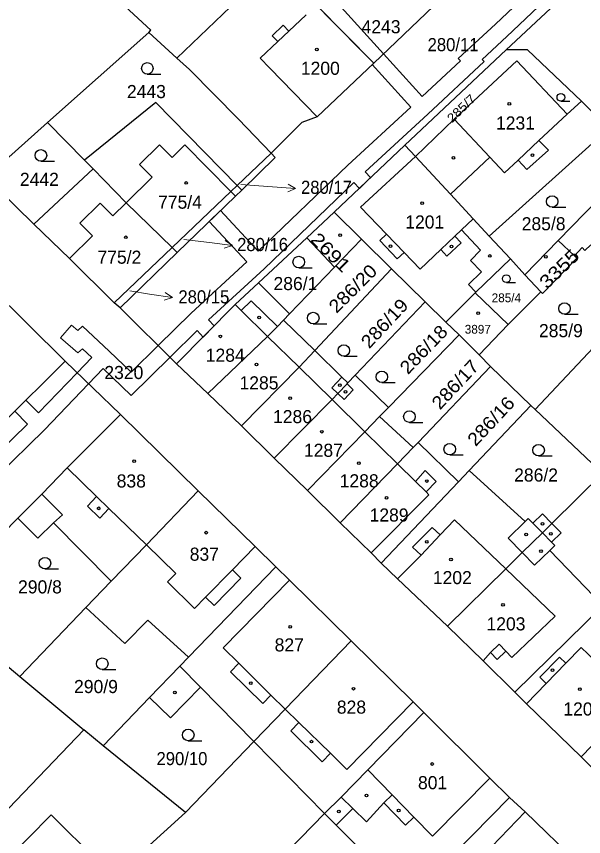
# Model space of a CAD drawing. Extents: x -679733 to -673243, y -1075091 to -1066557.
# Drawn here: x -676204.7 to -676131.1, y -1072172.5 to -1072066.1 of the extents above; entities that cross this region are included whole.
import ezdxf
from ezdxf.enums import TextEntityAlignment as Align

# ---------------------------------------------------------------- set-up
doc = ezdxf.new("R2010")
doc.units = 0
doc.header["$LTSCALE"] = 0.68
for name, color, linetype, lineweight in [('1', 7, 'Continuous', 25), ('13', 7, 'Continuous', 13), ('3', 7, 'Continuous', 25), ('4', 7, 'Continuous', 13), ('5', 7, 'Continuous', 25), ('7', 7, 'Continuous', 13)]:
    doc.layers.add(name, color=color, linetype=linetype, lineweight=lineweight)
doc.layers.add('2', color=7, linetype='Continuous')

msp = doc.modelspace()

# ---------------------------------------------------------------- linework, layer by layer
at = {"layer": '1'}
for p, q in [((-676176.01, -1072088.06), (-676171.6, -1072083.85)), ((-676195.82, -1072084.77), (-676194.71, -1072085.9)), ((-676194.71, -1072085.9), (-676202.38, -1072093.07)), ((-676202.38, -1072093.07), (-676208.61, -1072087)), ((-676175.42, -1072088.66), (-676176.01, -1072088.06)), ((-676134.34, -1072095.2), (-676138.69, -1072099.64)), ((-676134.34, -1072095.2), (-676132.25, -1072097.2)), ((-676183.78, -1072096.77), (-676184.45, -1072096.12)), ((-676138.69, -1072099.64), (-676140.56, -1072097.58)), ((-676169.21, -1072104.69), (-676163.38, -1072098.67)), ((-676155.97, -1072098.88), (-676165.92, -1072109.45)), ((-676191.21, -1072103.95), (-676191.96, -1072103.29)), ((-676147.22, -1072107.44), (-676148.94, -1072105.8)), ((-676160.68, -1072112.67), (-676161.64, -1072113.68)), ((-676137.89, -1072116.59), (-676145.92, -1072125.03)), ((-676191.15, -1072117.78), (-676181.06, -1072127.66)), ((-676147.31, -1072126.49), (-676152.54, -1072121.4)), ((-676171, -1072137.54), (-676182.33, -1072149.26)), ((-676192.35, -1072139.4), (-676195.64, -1072142.82)), ((-676139.96, -1072153.8), (-676128.56, -1072142.56)), ((-676204.23, -1072151.76), (-676195.92, -1072158.68)), ((-676193.42, -1072160.74), (-676187.38, -1072154.49))]:
    msp.add_line(p, q, dxfattribs=at)
for points in [[(-676187.49, -1072068.2), (-676187.22, -1072067.91), (-676195.57, -1072060.17), (-676182.33, -1072048.06), (-676174.16, -1072056.23)], [(-676142.14, -1072056.79), (-676146.87, -1072061.29), (-676150.53, -1072064.78), (-676158.28, -1072072.17)], [(-676172.04, -1072058.35), (-676173.81, -1072060.11), (-676172.9, -1072061.03), (-676183.84, -1072071.54)], [(-676158.28, -1072072.17), (-676165.74, -1072064.68), (-676172.04, -1072058.35)], [(-676154.24, -1072082.84), (-676141.11, -1072070.44), (-676132.12, -1072062.03)], [(-676183.84, -1072071.54), (-676187.49, -1072068.2), (-676200.62, -1072079.87)], [(-676131.34, -1072077.11), (-676138.34, -1072070.44), (-676141.11, -1072070.44)], [(-676171.6, -1072083.85), (-676175.82, -1072079.47), (-676182.21, -1072073.03), (-676183.84, -1072071.54)], [(-676158.28, -1072072.17), (-676165.63, -1072079.13), (-676167.61, -1072079.88), (-676171.6, -1072083.85)], [(-676131.34, -1072077.11), (-676133.21, -1072078.82), (-676139.74, -1072071.87), (-676147.84, -1072079.45), (-676152.89, -1072084.29)], [(-676176.01, -1072088.06), (-676186.55, -1072077.28), (-676195.82, -1072084.77)], [(-676143.32, -1072094.61), (-676127.77, -1072080.68), (-676131.34, -1072077.11)], [(-676195.82, -1072084.77), (-676200.62, -1072079.87), (-676208.61, -1072087)], [(-676143.32, -1072094.61), (-676145.38, -1072092.39), (-676148.34, -1072089.19), (-676152.89, -1072084.29), (-676154.24, -1072082.84), (-676163.44, -1072091.53), (-676159.88, -1072095.04), (-676155.97, -1072098.88), (-676151.61, -1072103.17), (-676148.94, -1072105.8), (-676145.14, -1072101.98)], [(-676171.6, -1072083.85), (-676171.07, -1072084.42), (-676175.42, -1072088.66)], [(-676114.59, -1072093.59), (-676123.94, -1072084.5), (-676134.34, -1072095.2)], [(-676184.45, -1072096.12), (-676190.41, -1072090.29), (-676194.71, -1072085.9)], [(-676184.45, -1072096.12), (-676176.82, -1072088.84), (-676176.01, -1072088.06)], [(-676175.42, -1072088.66), (-676176.24, -1072089.43), (-676183.78, -1072096.77), (-676191.21, -1072103.95), (-676183.87, -1072111.19)], [(-676183.87, -1072111.19), (-676176.26, -1072103.51), (-676173.24, -1072100.69), (-676166.97, -1072094.83), (-676163.44, -1072091.53)], [(-676202.38, -1072093.07), (-676197.78, -1072097.55), (-676191.96, -1072103.29), (-676184.45, -1072096.12)], [(-676166.97, -1072094.83), (-676163.38, -1072098.67), (-676159.88, -1072095.04)], [(-676145.14, -1072101.98), (-676145.03, -1072101.88), (-676140.56, -1072097.58), (-676143.32, -1072094.61)], [(-676123.37, -1072102.26), (-676127.8, -1072097.97), (-676128.41, -1072098.6), (-676129.86, -1072097.2), (-676129.25, -1072096.58), (-676130.1, -1072095.76), (-676130.89, -1072096.49), (-676131.25, -1072096.11), (-676132.25, -1072097.2)], [(-676132.25, -1072097.2), (-676131.94, -1072097.5), (-676136.41, -1072102.06), (-676136.6, -1072101.86)], [(-676209.98, -1072099.4), (-676208.01, -1072101.29), (-676198.33, -1072110.85)], [(-676145.14, -1072101.98), (-676140.84, -1072106.11), (-676136.6, -1072101.86), (-676138.69, -1072099.64)], [(-676170.01, -1072105.52), (-676169.21, -1072104.69), (-676173.24, -1072100.69)], [(-676151.61, -1072103.17), (-676160.68, -1072112.67), (-676156.39, -1072116.87)], [(-676179.8, -1072115.06), (-676172.07, -1072107.65), (-676170.8, -1072106.33), (-676170.01, -1072105.52)], [(-676175.46, -1072119.25), (-676167.97, -1072111.62), (-676165.92, -1072109.45), (-676170.01, -1072105.52)], [(-676140.84, -1072106.11), (-676144.61, -1072110.04), (-676143.14, -1072111.53), (-676137.89, -1072116.59), (-676137.33, -1072117.12), (-676127.04, -1072106.18)], [(-676144.61, -1072110.04), (-676147.22, -1072107.44), (-676156.39, -1072116.87)], [(-676161.64, -1072113.68), (-676162.44, -1072112.92), (-676165.92, -1072109.45)], [(-676198.33, -1072110.85), (-676206.41, -1072118.88), (-676207.52, -1072120.02), (-676210.03, -1072122.6)], [(-676204.47, -1072131.23), (-676201.38, -1072128.11), (-676198.08, -1072124.69), (-676191.15, -1072117.78), (-676198.33, -1072110.85)], [(-676157.34, -1072137.04), (-676158.61, -1072135.71), (-676162.64, -1072131.84), (-676166.9, -1072127.63), (-676171.21, -1072123.45), (-676175.46, -1072119.25), (-676179.8, -1072115.06), (-676183.87, -1072111.19)], [(-676156.39, -1072116.87), (-676157.53, -1072118.04), (-676153.18, -1072122.07), (-676152.54, -1072121.4), (-676143.14, -1072111.53)], [(-676171.21, -1072123.45), (-676163.7, -1072115.84), (-676162.94, -1072115.05), (-676161.74, -1072113.79), (-676161.64, -1072113.68)], [(-676135.17, -1072131.89), (-676128.56, -1072125.39), (-676129.15, -1072124.84), (-676137.33, -1072117.12)], [(-676166.9, -1072127.63), (-676159.44, -1072120.01), (-676157.53, -1072118.04)], [(-676162.64, -1072131.84), (-676155.19, -1072124.18), (-676153.18, -1072122.07)], [(-676135.17, -1072131.89), (-676136.39, -1072130.65), (-676137.63, -1072131.87), (-676138.24, -1072131.25), (-676138.66, -1072131.66), (-676145.92, -1072125.03), (-676147.31, -1072126.49), (-676157.34, -1072137.04)], [(-676181.06, -1072127.66), (-676187.8, -1072134.67), (-676192.35, -1072139.4)], [(-676181.06, -1072127.66), (-676173.69, -1072134.88), (-676171, -1072137.54)], [(-676215.59, -1072142.43), (-676210.44, -1072137.26), (-676204.47, -1072131.23)], [(-676204.47, -1072131.23), (-676201.87, -1072133.79), (-676199.83, -1072131.84), (-676192.35, -1072139.4)], [(-676148.74, -1072145.24), (-676141.16, -1072137.78), (-676139.02, -1072135.68), (-676136.41, -1072133.11), (-676135.17, -1072131.89)], [(-676128.56, -1072142.56), (-676135.46, -1072135.4), (-676134.8, -1072134.75), (-676135.21, -1072134.34), (-676133.95, -1072133.13), (-676135.17, -1072131.89)], [(-676157.34, -1072137.04), (-676155.2, -1072139.07), (-676148.74, -1072145.24)], [(-676171, -1072137.54), (-676169.21, -1072139.25), (-676161.24, -1072147.11)], [(-676211.14, -1072145.98), (-676204.23, -1072151.76), (-676195.64, -1072142.82)], [(-676195.64, -1072142.82), (-676190.61, -1072147.46), (-676187.6, -1072144.46), (-676182.33, -1072149.26)], [(-676148.74, -1072145.24), (-676144.1, -1072149.74), (-676139.96, -1072153.8)], [(-676173.85, -1072160.2), (-676169.79, -1072155.99), (-676161.24, -1072147.11)], [(-676161.24, -1072147.11), (-676153.17, -1072155.05), (-676151.81, -1072156.45)], [(-676182.33, -1072149.26), (-676183.45, -1072150.42), (-676187.38, -1072154.49)], [(-676131.37, -1072162.17), (-676124.26, -1072154.89), (-676122.99, -1072153.59), (-676118.96, -1072149.46)], [(-676187.38, -1072154.49), (-676184.65, -1072157.13), (-676180.78, -1072153.14), (-676173.85, -1072160.2)], [(-676139.96, -1072153.8), (-676138.45, -1072155.3), (-676131.37, -1072162.17)], [(-676151.81, -1072156.45), (-676159.06, -1072163.86), (-676162.53, -1072167.4), (-676164.67, -1072169.55)], [(-676151.81, -1072156.45), (-676143.23, -1072164.95), (-676140.68, -1072167.47)], [(-676195.92, -1072158.68), (-676206.62, -1072169.88), (-676212.97, -1072186.08), (-676224.5, -1072198.75)], [(-676182.71, -1072169.41), (-676193.42, -1072160.74), (-676195.92, -1072158.68)], [(-676172.49, -1072177.56), (-676164.67, -1072169.55), (-676173.85, -1072160.2), (-676182.71, -1072169.41), (-676199.6, -1072184.73), (-676189.24, -1072194.84), (-676188.86, -1072195.21)], [(-676131.37, -1072162.17), (-676125.17, -1072168.27), (-676122.73, -1072170.71)], [(-676152.8, -1072179.78), (-676152.34, -1072179.32), (-676150.36, -1072177.31), (-676140.68, -1072167.47)], [(-676140.68, -1072167.47), (-676138.62, -1072169.32), (-676131.77, -1072175.96)], [(-676164.67, -1072169.55), (-676163.17, -1072171.05), (-676156.88, -1072177.31), (-676157.28, -1072177.76), (-676153.99, -1072180.99), (-676152.8, -1072179.78)]]:
    msp.add_lwpolyline(points, dxfattribs=at)
msp.add_lwpolyline([(-676204.18, -1072182.37), (-676206.66, -1072179.88), (-676205.42, -1072178.57), (-676204.36, -1072177.5), (-676206.13, -1072175.75), (-676200.14, -1072169.72), (-676194.13, -1072175.69), (-676195.58, -1072177.16), (-676194.72, -1072178.01), (-676196.51, -1072179.84), (-676197.36, -1072178.99), (-676200.09, -1072181.72), (-676201.88, -1072179.97), (-676202.93, -1072181.04)], close=True, dxfattribs=at)
at = {"layer": '13'}
for points in [[(-676130.11, -1072055.39), (-676142.49, -1072067.14), (-676147.32, -1072071.59), (-676147.05, -1072071.88), (-676152, -1072076.51), (-676157.03, -1072070.98), (-676163.36, -1072064.02)], [(-676213.43, -1072131.86), (-676201.03, -1072119.77), (-676195.29, -1072113.79), (-676193.39, -1072111.81), (-676189.77, -1072115.3), (-676184.73, -1072110.34), (-676181.22, -1072106.89), (-676180.43, -1072107.72), (-676179, -1072106.27), (-676179.74, -1072105.49), (-676172.53, -1072098.87), (-676160.88, -1072087.68), (-676160.16, -1072088.43), (-676158.69, -1072087.04), (-676159.4, -1072086.29), (-676151.28, -1072078.79), (-676143.97, -1072071.96), (-676144.23, -1072071.69), (-676141.01, -1072068.72), (-676127.92, -1072056.29)], [(-676164.73, -1072065.7), (-676158.28, -1072072.17), (-676158.5, -1072072.38), (-676153.49, -1072077.89), (-676161.64, -1072085.41), (-676173.27, -1072096.59), (-676178.18, -1072091.32), (-676179.64, -1072092.74), (-676174.75, -1072097.98), (-676181.98, -1072104.62), (-676186.27, -1072108.83), (-676189.79, -1072112.28), (-676192.64, -1072109.53), (-676196.1, -1072106.32), (-676196.71, -1072106.89), (-676197.53, -1072106.18), (-676198.93, -1072107.82), (-676196.67, -1072109.77), (-676196.1, -1072109.26), (-676194.89, -1072110.39), (-676196.77, -1072112.35), (-676201.78, -1072117.57), (-676203.42, -1072115.91), (-676204.86, -1072117.34), (-676203.21, -1072119.01), (-676214.89, -1072130.4)]]:
    msp.add_lwpolyline(points, dxfattribs=at)
at = {"layer": '3'}
for p, q in [((-676187.673, -1072073.61), (-676185.923, -1072073.61)), ((-676134.005, -1072077.13), (-676132.833, -1072077.13)), ((-676201.483, -1072084.9), (-676199.733, -1072084.9)), ((-676135.133, -1072090.89), (-676133.383, -1072090.89)), ((-676168.023, -1072098.74), (-676166.273, -1072098.74)), ((-676141.075, -1072100.65), (-676139.903, -1072100.65)), ((-676133.533, -1072104.77), (-676131.783, -1072104.77)), ((-676166.143, -1072106), (-676164.393, -1072106)), ((-676162.173, -1072110.21), (-676160.423, -1072110.21)), ((-676157.243, -1072113.63), (-676155.493, -1072113.63)), ((-676153.663, -1072118.79), (-676151.913, -1072118.79)), ((-676148.433, -1072123.01), (-676146.683, -1072123.01)), ((-676136.903, -1072123.15), (-676135.153, -1072123.15)), ((-676200.953, -1072137.8), (-676199.203, -1072137.8)), ((-676193.513, -1072150.85), (-676191.763, -1072150.85)), ((-676182.363, -1072160.09), (-676180.613, -1072160.09))]:
    msp.add_line(p, q, dxfattribs=at)
for centre, radius in [((-676187.6729, -1072072.8598), 0.75), ((-676134.0052, -1072076.6274), 0.5025), ((-676201.4829, -1072084.1498), 0.75), ((-676135.1329, -1072090.1398), 0.75), ((-676168.0229, -1072097.9898), 0.75), ((-676141.0752, -1072100.1474), 0.5025), ((-676133.5329, -1072104.0198), 0.75), ((-676166.1429, -1072105.2498), 0.75), ((-676162.1729, -1072109.4598), 0.75), ((-676157.2429, -1072112.8798), 0.75), ((-676153.6629, -1072118.0398), 0.75), ((-676148.4329, -1072122.2598), 0.75), ((-676136.9029, -1072122.3998), 0.75), ((-676200.9529, -1072137.0498), 0.75), ((-676193.5129, -1072150.0998), 0.75), ((-676182.3629, -1072159.3398), 0.75)]:
    msp.add_circle(centre, radius, dxfattribs=at)
at = {"layer": '4'}
for p, q in [((-676169.33, -1072068.04), (-676167.07, -1072065.92)), ((-676169.33, -1072068.04), (-676170.74, -1072069.38)), ((-676173.02, -1072071.54), (-676170.74, -1072069.38)), ((-676170.74, -1072069.38), (-676171.46, -1072068.63)), ((-676171.76, -1072072.85), (-676173.02, -1072071.54)), ((-676165.63, -1072079.13), (-676171.76, -1072072.85)), ((-676133.21, -1072078.82), (-676136.85, -1072082.23)), ((-676143.22, -1072084.37), (-676147.84, -1072079.45)), ((-676188.69, -1072085.33), (-676186.1, -1072082.79)), ((-676186.1, -1072082.79), (-676184.47, -1072084.44)), ((-676184.47, -1072084.44), (-676182.79, -1072082.78)), ((-676182.79, -1072082.78), (-676176.82, -1072088.84)), ((-676139.56, -1072084.78), (-676136.85, -1072082.23)), ((-676136.85, -1072082.23), (-676135.61, -1072083.46)), ((-676152.89, -1072084.29), (-676159.99, -1072090.86)), ((-676135.61, -1072083.46), (-676138.42, -1072086)), ((-676187.06, -1072086.99), (-676188.69, -1072085.33)), ((-676148.34, -1072089.19), (-676143.22, -1072084.37)), ((-676141.31, -1072086.41), (-676143.22, -1072084.37)), ((-676139.56, -1072084.78), (-676141.31, -1072086.41)), ((-676138.42, -1072086), (-676139.56, -1072084.78)), ((-676190.41, -1072090.29), (-676187.06, -1072086.99)), ((-676176.82, -1072088.84), (-676176.24, -1072089.43)), ((-676196.41, -1072092.95), (-676193.79, -1072090.36)), ((-676193.79, -1072090.36), (-676192.16, -1072092.01)), ((-676192.16, -1072092.01), (-676190.41, -1072090.29)), ((-676159.99, -1072090.86), (-676156.63, -1072094.37)), ((-676146.9, -1072093.83), (-676145.38, -1072092.39)), ((-676194.78, -1072094.6), (-676196.41, -1072092.95)), ((-676147.76, -1072094.64), (-676146.9, -1072093.83)), ((-676146.9, -1072093.83), (-676144.44, -1072096.43)), ((-676197.78, -1072097.55), (-676194.78, -1072094.6)), ((-676156.63, -1072094.37), (-676157.49, -1072095.19)), ((-676154.36, -1072096.74), (-676156.63, -1072094.37)), ((-676147.76, -1072094.64), (-676149.6, -1072096.38)), ((-676146.96, -1072095.48), (-676147.76, -1072094.64)), ((-676157.49, -1072095.19), (-676155.24, -1072097.59)), ((-676148.81, -1072097.23), (-676146.96, -1072095.48)), ((-676155.24, -1072097.59), (-676154.36, -1072096.74)), ((-676154.36, -1072096.74), (-676152.28, -1072098.91)), ((-676152.28, -1072098.91), (-676149.6, -1072096.38)), ((-676149.6, -1072096.38), (-676148.81, -1072097.23)), ((-676145.72, -1072097.8), (-676144.44, -1072096.43)), ((-676144.3, -1072099.26), (-676145.72, -1072097.8)), ((-676145.98, -1072100.91), (-676144.3, -1072099.26)), ((-676145.03, -1072101.88), (-676145.98, -1072100.91)), ((-676175.48, -1072104.28), (-676174.21, -1072103)), ((-676174.21, -1072103), (-676170.8, -1072106.33)), ((-676176.26, -1072103.51), (-676175.48, -1072104.28)), ((-676175.48, -1072104.28), (-676172.07, -1072107.65)), ((-676172.07, -1072107.65), (-676167.97, -1072111.62)), ((-676167.97, -1072111.62), (-676163.7, -1072115.84)), ((-676163.74, -1072114.29), (-676162.44, -1072112.92)), ((-676161.74, -1072113.79), (-676160.95, -1072114.55)), ((-676162.94, -1072115.05), (-676163.74, -1072114.29)), ((-676162.14, -1072115.81), (-676162.94, -1072115.05)), ((-676160.95, -1072114.55), (-676162.14, -1072115.81)), ((-676163.7, -1072115.84), (-676159.44, -1072120.01)), ((-676155.19, -1072124.18), (-676159.44, -1072120.01)), ((-676194.25, -1072128.41), (-676198.08, -1072124.69)), ((-676152.87, -1072126.46), (-676155.19, -1072124.18)), ((-676151.6, -1072125.02), (-676152.87, -1072126.46)), ((-676150.17, -1072126.45), (-676151.6, -1072125.02)), ((-676152.87, -1072126.46), (-676151.5, -1072127.8)), ((-676151.5, -1072127.8), (-676150.17, -1072126.45)), ((-676151.12, -1072128.17), (-676151.5, -1072127.8)), ((-676198.7, -1072130.77), (-676201.38, -1072128.11)), ((-676195.45, -1072129.65), (-676194.25, -1072128.41)), ((-676194.25, -1072128.41), (-676192.65, -1072129.97)), ((-676158.61, -1072135.71), (-676151.12, -1072128.17)), ((-676193.85, -1072131.2), (-676195.45, -1072129.65)), ((-676192.65, -1072129.97), (-676193.85, -1072131.2)), ((-676187.8, -1072134.67), (-676192.65, -1072129.97)), ((-676199.83, -1072131.84), (-676198.7, -1072130.77)), ((-676147.83, -1072131.42), (-676149.68, -1072133.39)), ((-676141.16, -1072137.78), (-676147.83, -1072131.42)), ((-676138.66, -1072131.66), (-676140.85, -1072133.82)), ((-676136.41, -1072133.11), (-676137.63, -1072131.87)), ((-676150.71, -1072132.42), (-676153.24, -1072134.97)), ((-676149.68, -1072133.39), (-676150.71, -1072132.42)), ((-676135.21, -1072134.34), (-676136.41, -1072133.11)), ((-676152.14, -1072136.01), (-676149.68, -1072133.39)), ((-676140.85, -1072133.82), (-676139.02, -1072135.68)), ((-676187.8, -1072134.67), (-676183.99, -1072138.39)), ((-676176.64, -1072137.9), (-676173.69, -1072134.88)), ((-676153.24, -1072134.97), (-676152.14, -1072136.01)), ((-676137.41, -1072137.32), (-676135.46, -1072135.4)), ((-676152.14, -1072136.01), (-676155.2, -1072139.07)), ((-676139.02, -1072135.68), (-676137.41, -1072137.32)), ((-676183.99, -1072138.39), (-676185.06, -1072139.49)), ((-676176.64, -1072137.9), (-676180.13, -1072141.48)), ((-676175.53, -1072138.98), (-676176.64, -1072137.9)), ((-676134.74, -1072143.91), (-676141.16, -1072137.78)), ((-676185.06, -1072139.49), (-676181.54, -1072142.92)), ((-676179.02, -1072142.56), (-676175.53, -1072138.98)), ((-676169.21, -1072139.25), (-676177.82, -1072148.04)), ((-676181.54, -1072142.92), (-676180.13, -1072141.48)), ((-676180.13, -1072141.48), (-676179.02, -1072142.56)), ((-676140.37, -1072149.29), (-676134.74, -1072143.91)), ((-676177.82, -1072148.04), (-676175.8, -1072150.03)), ((-676143.13, -1072148.64), (-676142.01, -1072147.57)), ((-676142.01, -1072147.57), (-676141.14, -1072148.48)), ((-676131.36, -1072147.98), (-676133.36, -1072150.05)), ((-676128.34, -1072150.92), (-676131.36, -1072147.98)), ((-676144.1, -1072149.74), (-676143.13, -1072148.64)), ((-676142.26, -1072149.55), (-676143.13, -1072148.64)), ((-676141.14, -1072148.48), (-676142.26, -1072149.55)), ((-676141.14, -1072148.48), (-676140.37, -1072149.29)), ((-676136.75, -1072151.83), (-676134.19, -1072149.23)), ((-676134.19, -1072149.23), (-676133.36, -1072150.05)), ((-676175.8, -1072150.03), (-676176.88, -1072151.14)), ((-676133.36, -1072150.05), (-676135.9, -1072152.67)), ((-676180.78, -1072153.14), (-676183.45, -1072150.42)), ((-676176.88, -1072151.14), (-676172.7, -1072155.24)), ((-676135.9, -1072152.67), (-676136.75, -1072151.83)), ((-676135.9, -1072152.67), (-676138.45, -1072155.3)), ((-676171.65, -1072154.17), (-676169.79, -1072155.99)), ((-676161.77, -1072163.81), (-676153.17, -1072155.05)), ((-676169.79, -1072155.99), (-676168.01, -1072157.74)), ((-676168.01, -1072157.74), (-676169.07, -1072158.82)), ((-676163.91, -1072161.71), (-676168.01, -1072157.74)), ((-676169.07, -1072158.82), (-676165, -1072162.82)), ((-676165, -1072162.82), (-676163.91, -1072161.71)), ((-676163.91, -1072161.71), (-676161.77, -1072163.81)), ((-676155.9, -1072167.1), (-676159.06, -1072163.86)), ((-676150.67, -1072172.46), (-676143.23, -1072164.95)), ((-676156.97, -1072168.15), (-676155.9, -1072167.1)), ((-676153.08, -1072169.99), (-676155.9, -1072167.1)), ((-676161.02, -1072168.88), (-676162.53, -1072167.4)), ((-676159.23, -1072170.63), (-676156.97, -1072168.15)), ((-676156.97, -1072168.15), (-676154.15, -1072171.04)), ((-676163.17, -1072171.05), (-676161.02, -1072168.88)), ((-676161.02, -1072168.88), (-676159.23, -1072170.63)), ((-676145.34, -1072176.25), (-676138.62, -1072169.32)), ((-676154.15, -1072171.04), (-676153.08, -1072169.99)), ((-676153.08, -1072169.99), (-676150.67, -1072172.46))]:
    msp.add_line(p, q, dxfattribs=at)
for points in [[(-676171.46, -1072068.63), (-676170.05, -1072067.27), (-676169.33, -1072068.04)], [(-676172.7, -1072155.24), (-676171.65, -1072154.17), (-676175.8, -1072150.03)]]:
    msp.add_lwpolyline(points, dxfattribs=at)
at = {"layer": '5'}
for centre in [(-676165.6768, -1072070.3992), (-676140.6968, -1072077.4492), (-676147.9568, -1072084.4692), (-676137.7068, -1072084.1292), (-676182.6468, -1072087.7292), (-676152.0068, -1072090.3592), (-676190.4568, -1072094.7792), (-676162.6568, -1072094.4892), (-676156.1068, -1072095.9192), (-676148.1868, -1072095.9692), (-676143.2368, -1072097.1992), (-676135.9468, -1072097.3192), (-676144.7368, -1072104.6092), (-676173.1468, -1072105.1892), (-676178.1968, -1072107.6292), (-676173.5068, -1072111.2892), (-676162.6868, -1072113.9692), (-676161.9668, -1072114.8292), (-676169.1368, -1072115.6592), (-676165.0168, -1072119.9992), (-676189.3868, -1072123.8292), (-676160.2368, -1072124.0692), (-676151.3868, -1072126.3992), (-676156.6168, -1072128.5892), (-676193.9868, -1072129.9392), (-676136.3768, -1072131.9592), (-676180.0268, -1072133.0992), (-676138.5168, -1072133.3492), (-676135.3068, -1072133.2392), (-676151.4168, -1072134.2792), (-676136.5868, -1072135.4892), (-676148.2668, -1072136.5692), (-676141.5168, -1072142.4592), (-676169.1168, -1072145.3092), (-676135.0868, -1072150.9292), (-676174.2568, -1072152.6292), (-676160.9168, -1072153.3392), (-676131.5568, -1072153.3992), (-676184.0868, -1072153.8292), (-676166.3668, -1072160.2092), (-676150.7068, -1072163.1092), (-676159.2268, -1072167.1892), (-676162.8168, -1072169.2592), (-676155.0568, -1072169.1292)]:
    msp.add_circle(centre, 0.175, dxfattribs=at)
at = {"layer": '7'}
for p, q in [((-676168.426, -1072088.439), (-676169.39, -1072087.87)), ((-676176.641, -1072095.826), (-676177.574, -1072095.207)), ((-676184.426, -1072102.609), (-676185.337, -1072101.958))]:
    msp.add_line(p, q, dxfattribs=at)
for points in [[(-676175.52, -1072087.94), (-676171.42, -1072088.23), (-676168.426, -1072088.439), (-676169.46, -1072088.869)], [(-676182.93, -1072095.07), (-676179.62, -1072095.46), (-676176.641, -1072095.826), (-676177.696, -1072096.201)], [(-676189.93, -1072101.73), (-676187.39, -1072102.14), (-676184.426, -1072102.609), (-676185.493, -1072102.947)]]:
    msp.add_lwpolyline(points, dxfattribs=at)

# ---------------------------------------------------------------- texts
at = {"layer": '2'}
msp.add_text('4243', height=1.7, dxfattribs=at).set_placement((-676157.34, -1072068.31), align=Align.CENTER)
at = {"layer": '2', "width": 0.95}
for s, p in [('280/11', (-676151.3, -1072070.63)), ('280/17', (-676167.73, -1072089.143)), ('280/16', (-676176.02, -1072096.563)), ('280/15', (-676183.64, -1072103.353)), ('290/10', (-676186.48, -1072163.259))]:
    msp.add_text(s, height=1.7, dxfattribs=at).set_placement(p)
at = {"layer": '2'}
for s, height, p in [('1200', 1.7, (-676167.75, -1072073.7)), ('2443', 1.7, (-676190.32, -1072076.72)), ('1231', 1.7, (-676142.43, -1072080.8)), ('2442', 1.7, (-676204.21, -1072088.11)), ('775/4', 1.7, (-676186.28, -1072091.07)), ('1201', 1.7, (-676154.2, -1072093.64)), ('285/8', 1.7, (-676139.09, -1072093.87)), ('775/2', 1.7, (-676194.14, -1072098.21)), ('286/1', 1.7, (-676171.3, -1072101.63)), ('285/4', 1.14, (-676142.99, -1072103.199)), ('3897', 1.14, (-676146.48, -1072107.28)), ('285/9', 1.7, (-676136.85, -1072107.739)), ('1284', 1.7, (-676180.09, -1072110.92)), ('2320', 1.7, (-676193.25, -1072113.17)), ('1285', 1.7, (-676175.71, -1072114.509)), ('1286', 1.7, (-676171.36, -1072118.89)), ('1287', 1.7, (-676167.35, -1072123.259)), ('286/2', 1.7, (-676140.07, -1072126.47)), ('838', 1.7, (-676191.65, -1072127.239)), ('1288', 1.7, (-676162.71, -1072127.22)), ('1289', 1.7, (-676158.83, -1072131.66)), ('837', 1.7, (-676182.17, -1072136.739)), ('1202', 1.7, (-676150.62, -1072139.779)), ('290/8', 1.7, (-676204.45, -1072140.979)), ('1203', 1.7, (-676143.66, -1072145.779)), ('827', 1.7, (-676171.15, -1072148.509)), ('290/9', 1.7, (-676197.18, -1072153.91)), ('828', 1.7, (-676163.08, -1072156.58)), ('1204', 1.7, (-676133.69, -1072156.82)), ('801', 1.7, (-676152.55, -1072166.38))]:
    msp.add_text(s, height=height, dxfattribs=at).set_placement(p)
for s, height, rotation, width, p in [('285/7', 1.14, 44, 1.15, (-676148.114, -1072079.98)), ('2691', 1.7, 315, 1.2, (-676166.621, -1072095.191)), ('3355', 1.7, 44, 1.2, (-676135.809, -1072101.581)), ('286/20', 1.7, 45, 1.1, (-676163.108, -1072104.731)), ('286/19', 1.7, 47, 1.1, (-676158.878, -1072109.319)), ('286/18', 1.7, 46, 1.1, (-676153.858, -1072112.67)), ('286/17', 1.7, 47, 1.1, (-676149.698, -1072117.259)), ('286/16', 1.7, 47, 1.1, (-676145.068, -1072122.009))]:
    msp.add_text(s, height=height, rotation=rotation, dxfattribs=dict(at, width=width)).set_placement(p)

doc.saveas('drawing.dxf')
